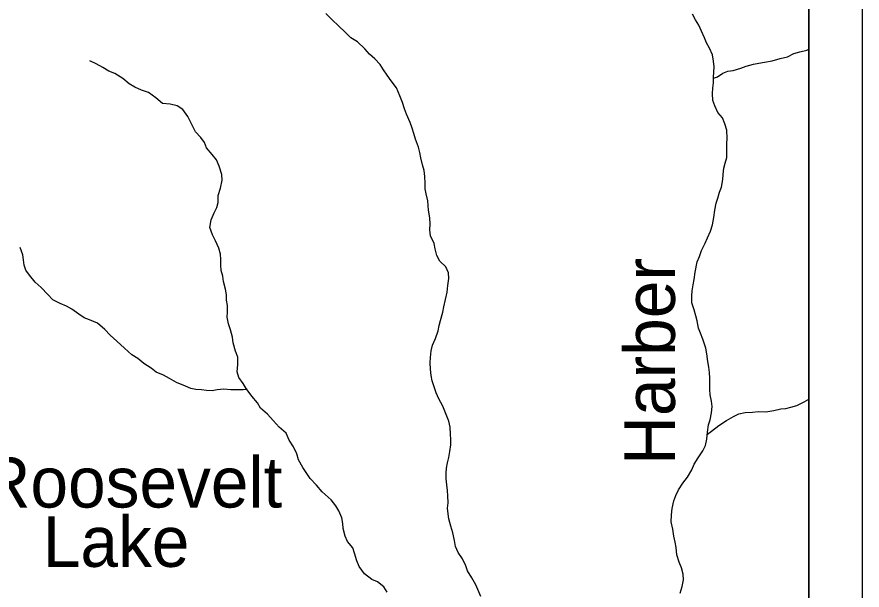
# Model space of a CAD drawing. Extents: x 0 to 34, y 0 to 22.
# Drawn here: x 7.417 to 9, y 16.283 to 17.355 of the extents above; entities that cross this region are included whole.
import ezdxf

# ---------------------------------------------------------------- set-up
doc = ezdxf.new("R2010")
doc.units = 0
for name, color, linetype in [('Default', 7, 'Continuous'), ('GM_X_Minor_Lake_Text', 7, 'Continuous'), ('GM_X_Minor_River', 7, 'Continuous'), ('GM_X_Minor_River_Text', 7, 'Continuous'), ('SH_Cut_Line', 7, 'Continuous'), ('SH_Data', 7, 'Continuous')]:
    doc.layers.add(name, color=color, linetype=linetype)

msp = doc.modelspace()

# ---------------------------------------------------------------- linework, layer by layer
at = {"layer": 'Default'}
msp.add_lwpolyline([(8.9, 14.1), (8.9, 18.9397), (8.8678, 19.0216), (8.806, 19.0402), (8.8461, 19.2253)], dxfattribs=at)
at = {"layer": 'GM_X_Minor_River'}
for points in [[(8.286, 16.2709), (8.2763, 16.2923), (8.2691, 16.3056), (8.2612, 16.3189), (8.2579, 16.3284), (8.2519, 16.3414), (8.2432, 16.3532), (8.2387, 16.3642), (8.2369, 16.3756), (8.2335, 16.3901), (8.2298, 16.4026), (8.2261, 16.416), (8.2246, 16.4255), (8.2236, 16.4361), (8.2248, 16.4463), (8.2241, 16.4593), (8.2234, 16.4688), (8.2223, 16.4794), (8.2213, 16.4912), (8.2209, 16.5014), (8.2218, 16.5109), (8.2237, 16.5208), (8.2261, 16.531), (8.228, 16.542), (8.2296, 16.5545), (8.2297, 16.5644), (8.2294, 16.5747), (8.2287, 16.5876), (8.2261, 16.5986), (8.2197, 16.6142), (8.2149, 16.6268), (8.207, 16.6405), (8.2021, 16.6519), (8.1984, 16.6629), (8.195, 16.674), (8.1932, 16.6839), (8.1914, 16.696), (8.1911, 16.7078), (8.1915, 16.7177), (8.1931, 16.7306), (8.1954, 16.7412), (8.2012, 16.7537), (8.2059, 16.7677), (8.2078, 16.7776), (8.2106, 16.7874), (8.2145, 16.8026), (8.2168, 16.8128), (8.2195, 16.8261), (8.2227, 16.8401), (8.2243, 16.8527), (8.2259, 16.8659), (8.2252, 16.8762), (8.2203, 16.8872), (8.209, 16.8979), (8.2033, 16.909), (8.2004, 16.9211), (8.1985, 16.9314), (8.1918, 16.9455), (8.1907, 16.9565), (8.1908, 16.9672), (8.1905, 16.9793), (8.1879, 16.9934), (8.1865, 17.0112), (8.1835, 17.0242), (8.1817, 17.0337), (8.1814, 17.0443), (8.1811, 17.0564), (8.1796, 17.0675), (8.1766, 17.0781), (8.1737, 17.0914), (8.1718, 17.1013), (8.1689, 17.1116), (8.1636, 17.1264), (8.1603, 17.1367), (8.1573, 17.1466), (8.1536, 17.1576), (8.1468, 17.1732), (8.1427, 17.1831), (8.139, 17.1949), (8.1345, 17.2071), (8.1281, 17.2223), (8.1183, 17.2357), (8.1108, 17.2463), (8.1036, 17.2563), (8.0976, 17.2658), (8.0874, 17.2765), (8.0776, 17.2856), (8.0685, 17.2956), (8.0549, 17.3082), (8.0424, 17.3162), (8.0326, 17.3258), (8.019, 17.3391), (8.008, 17.3491), (7.9956, 17.3613)], [(8.7216, 17.2417), (8.7225, 17.2524), (8.7229, 17.2618), (8.7218, 17.2725), (8.7196, 17.2839), (8.7144, 17.2965), (8.7087, 17.3064), (8.7046, 17.3159), (8.6994, 17.3281), (8.6941, 17.3395), (8.6877, 17.3494), (8.6825, 17.3604)], [(8.7216, 17.2402), (8.7289, 17.2432), (8.7392, 17.2496), (8.7487, 17.2533), (8.7586, 17.2548), (8.7731, 17.2593), (8.783, 17.263), (8.7967, 17.2664), (8.8066, 17.2686), (8.8172, 17.2704), (8.8317, 17.273), (8.8465, 17.2775), (8.8606, 17.2804), (8.8721, 17.2864), (8.8831, 17.2894), (8.8964, 17.2928), (8.9, 17.2949)], [(7.5658, 17.2673), (7.5537, 17.2727)], [(8.1104, 16.2788), (8.1044, 16.2887), (8.0927, 16.2982), (8.0817, 16.3025), (8.0681, 16.3132), (8.0579, 16.3269), (8.0538, 16.3376), (8.0493, 16.352), (8.0463, 16.3619), (8.0362, 16.3737), (8.032, 16.3836), (8.0283, 16.3981), (8.0276, 16.4076), (8.0254, 16.4179), (8.0202, 16.4308), (8.0141, 16.4403), (8.0055, 16.4518), (7.9885, 16.4667), (7.9783, 16.4793), (7.9662, 16.4915), (7.9587, 16.5029), (7.9526, 16.5124), (7.9444, 16.5262), (7.9414, 16.5376), (7.935, 16.5509), (7.9271, 16.5631), (7.9215, 16.5764), (7.9082, 16.5875), (7.8973, 16.6001), (7.8863, 16.6119), (7.8731, 16.6234), (7.8679, 16.6333), (7.8573, 16.6455), (7.8467, 16.6596), (7.8407, 16.6691), (7.8328, 16.6806), (7.8298, 16.6912), (7.8307, 16.7045), (7.8308, 16.7182), (7.8263, 16.73), (7.8222, 16.7452), (7.8207, 16.7562), (7.8174, 16.7699), (7.8133, 16.7806), (7.8107, 16.7931), (7.8115, 16.8034), (7.8112, 16.8151), (7.8098, 16.8254), (7.8094, 16.8349), (7.808, 16.8459), (7.8039, 16.86), (7.8028, 16.8702), (7.7998, 16.8805), (7.7991, 16.8904), (7.7992, 16.9014), (7.7981, 16.9113), (7.7952, 16.9227), (7.7888, 16.936), (7.7831, 16.9471), (7.7783, 16.9608), (7.7807, 16.9752), (7.7864, 16.9884), (7.7918, 16.9983), (7.7938, 17.0078), (7.7942, 17.0207), (7.7981, 17.0347), (7.8013, 17.0499), (7.801, 17.0601), (7.7961, 17.0757), (7.7912, 17.0879), (7.7829, 17.0978), (7.7724, 17.1104), (7.7683, 17.1199), (7.7615, 17.1295), (7.7517, 17.1398), (7.7449, 17.1539), (7.7374, 17.1687), (7.7276, 17.1817), (7.717, 17.1889), (7.7041, 17.1921), (7.6896, 17.1933), (7.6775, 17.2036), (7.6635, 17.2139), (7.6506, 17.2182), (7.6381, 17.2239), (7.6272, 17.2297), (7.6154, 17.24), (7.6007, 17.2492), (7.5893, 17.2538), (7.5783, 17.2607), (7.5658, 17.2673)], [(8.659, 16.2768), (8.6632, 16.2897), (8.6656, 16.3022), (8.6649, 16.3125), (8.6619, 16.3246), (8.6574, 16.3349), (8.653, 16.349), (8.6515, 16.3623), (8.6501, 16.3722), (8.6475, 16.3836), (8.6453, 16.3969), (8.6427, 16.4102), (8.6428, 16.4238), (8.6444, 16.4356), (8.6475, 16.45), (8.6514, 16.4595), (8.6564, 16.4701), (8.6641, 16.483), (8.6733, 16.4943), (8.6809, 16.5075), (8.6856, 16.5185), (8.6929, 16.5299), (8.7017, 16.5431), (8.7067, 16.553), (8.7094, 16.5651), (8.7106, 16.578), (8.7126, 16.5917), (8.7154, 16.6015), (8.7181, 16.6144), (8.7189, 16.6262), (8.7179, 16.6364), (8.7156, 16.6482), (8.7149, 16.6577), (8.7146, 16.6691), (8.7147, 16.679), (8.714, 16.6896), (8.7129, 16.6995), (8.7111, 16.7102), (8.7093, 16.7246), (8.7075, 16.7356), (8.7015, 16.752), (8.6974, 16.7634), (8.6936, 16.7729), (8.691, 16.7866), (8.6888, 16.7961), (8.6855, 16.8071), (8.6814, 16.8201), (8.6811, 16.8334), (8.6819, 16.8428), (8.6835, 16.8539), (8.6854, 16.8637), (8.6871, 16.8774), (8.691, 16.8971), (8.6952, 16.9069), (8.6995, 16.9179), (8.706, 16.9316), (8.7106, 16.9418), (8.716, 16.9543), (8.7199, 16.966), (8.7223, 16.9797), (8.7243, 16.9937), (8.727, 17.0063), (8.7301, 17.0161), (8.7332, 17.0271), (8.7367, 17.0366), (8.7394, 17.0506), (8.7399, 17.0601), (8.7411, 17.0723), (8.7434, 17.0817), (8.7469, 17.0923), (8.7466, 17.1034), (8.7467, 17.1174), (8.7475, 17.128), (8.7465, 17.1429), (8.7431, 17.155), (8.7383, 17.1664), (8.73, 17.176), (8.724, 17.1889), (8.7206, 17.1984), (8.7196, 17.2117), (8.7204, 17.222), (8.7216, 17.2315), (8.7216, 17.2417)], [(7.8482, 16.6577), (7.841, 16.6574), (7.8277, 16.6571), (7.8178, 16.6575), (7.8045, 16.6587), (7.792, 16.6573), (7.7825, 16.6558), (7.7722, 16.6562), (7.7627, 16.6574), (7.7524, 16.6583), (7.7426, 16.6598), (7.7327, 16.6641), (7.716, 16.6714), (7.7028, 16.6783), (7.6914, 16.6848), (7.6781, 16.6906), (7.6683, 16.6982), (7.6547, 16.7066), (7.6437, 16.7158), (7.6324, 16.7231), (7.6184, 16.7353), (7.6044, 16.7483), (7.5919, 16.7594), (7.5817, 16.7705), (7.5681, 16.7819), (7.5529, 16.7881), (7.5431, 16.7923), (7.5328, 16.7992), (7.52, 16.8084), (7.5101, 16.8142), (7.498, 16.8188), (7.4844, 16.8257), (7.4753, 16.836), (7.4625, 16.849), (7.4515, 16.8589), (7.4405, 16.8719), (7.4341, 16.8814), (7.4308, 16.8909), (7.4297, 16.9004), (7.4282, 16.9099), (7.4234, 16.9236)], [(8.7103, 16.5743), (8.7179, 16.5799), (8.7316, 16.5904), (8.7458, 16.5998), (8.7591, 16.6077), (8.7694, 16.6126), (8.7812, 16.6152), (8.7945, 16.6159), (8.8052, 16.6166), (8.82, 16.6165), (8.8344, 16.6187), (8.8478, 16.6217), (8.8573, 16.6227), (8.8668, 16.625), (8.8775, 16.6283), (8.8912, 16.6351), (8.9, 16.6401)]]:
    msp.add_lwpolyline(points, dxfattribs=at)
at = {"layer": 'SH_Cut_Line'}
msp.add_lwpolyline([(2.4352, 14.1), (8.9, 14.1), (8.9, 20.9), (2.4845, 20.9), (2.4809, 20.6393), (2.4757, 20.2566), (2.4573, 18.9074), (2.4581, 18.1825), (2.4581, 18.1772), (2.4586, 17.7785), (2.4545, 17.2795), (2.4313, 15.0183), (2.4372, 14.2719)], close=True, dxfattribs=at)
at = {"layer": 'SH_Data'}
for p, q in [((9, 21), (9, 14)), ((8.9, 20.9), (8.9, 14.1))]:
    msp.add_line(p, q, dxfattribs=at)

# ---------------------------------------------------------------- texts
at = {"layer": 'GM_X_Minor_Lake_Text'}
for s, rotation, p in [('Roosevelt', 0.0024, (7.351, 16.4372)), ('Lake', 0.0025, (7.4656, 16.3262))]:
    msp.add_text(s, height=0.0947, rotation=rotation, dxfattribs=at).set_placement(p)
at = {"layer": 'GM_X_Minor_River_Text'}
msp.add_text('Harber', height=0.0947, rotation=90.0024, dxfattribs=at).set_placement((8.6495, 16.5169))

doc.saveas('drawing.dxf')
